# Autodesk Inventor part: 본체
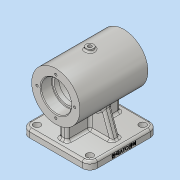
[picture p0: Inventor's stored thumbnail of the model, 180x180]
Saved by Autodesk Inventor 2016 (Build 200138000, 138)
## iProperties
Created: 2019-06
Part Number: 본체
Material: 알루미늄 6061
Document SubType Name: Modeling
Designer: Administrator
Mass: 610.373 g
Surface Area: 622.717 cm^2
Volume: 226.064 cm^3
Density: 2.7 g/cm^3
Appearance: 알루미늄 - 평지
Author: Administrator
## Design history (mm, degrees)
sketch "스케치1"
  geometry: C1 r 32 at (0, 0); 1 further point
  constraints: 1 centre point, 1 coincident
  dimensions: "d0" = 64 diameter of C1
extrude "돌출1" new body sketch "스케치1" stored distance "d1" = 90; taper "d2" = 0 deg
sketch "스케치2"
  geometry: L1 (45, -55)-(-45, -55); L2 (-45, -55)-(-45, -65); L3 (-45, -65)-(45, -65); L4 (45, -65)-(45, -55); 2 further points
  constraints: 8 end point, 2 parallel, 1 horizontal, 1 midpoint, 1 perpendicular, 1 vertical alignment
  dimensions: "d3" = 90 distance of L2.end L3.end; "d4" = 10 distance of L1.end L2.end; "d5" = 65 distance from line of L3 point (0, 0)
extrude "돌출2" join sketch "스케치2" stored distance "d6" = 90; taper "d7" = 0 deg
sketch "스케치3"
  geometry: L1 (40, -10)-(50, -10); L2 (50, -10)-(50, -80); L3 (50, -80)-(40, -80); L4 (40, -80)-(40, -10); L5 (40, -10)-(50, -80); L6 (50, -10)-(40, -80); 1 further point
  constraints: 12 end point, 2 midpoint, 2 parallel, 1 horizontal, 1 perpendicular
  dimensions: "d8" = 10 distance of L2.end L3.end; "d9" = 70 distance of L1.end L2.end
extrude "돌출3" join sketch "스케치3" stored distance "d10" = 90; taper "d11" = 0 deg
sketch "스케치4"
  geometry: L1 (45, -55)-(-45, -55) reference; L2 (-35, -55)-(-28.281, -36.539); L3 (-45, -55)-(-45, -65) reference; 1 further point
  constraints: 2 end point, 1 point on line
  dimensions: "d12" = 110 deg angle of L1 L2; "d13" = 10 distance from line of L3 L2.start
feature "리브1" sketch "스케치4" dims "d14" = 1, "d15" = 10, "d16" = 0, "d17" = 0, "d18" = 1, "d19" = 1
sketch "스케치5"
  geometry: L1 (-45, 32)-(-45, -32) reference; L2 (-45, 0)-(45, 0); L3 (45, -32)-(45, 32) reference; L4 (-45, 0)-(-45, 20); L5 (-45, 20)-(-30, 20); L6 (-30, 20)-(-30, 17); L7 (-30, 17)-(-24, 17); L8 (-24, 17)-(-24, 25); L9 (-24, 25)-(24, 25); L10 (24, 25)-(24, 17); L11 (24, 17)-(30, 17); L12 (30, 17)-(30, 20); L13 (30, 20)-(45, 20); L14 (45, 20)-(45, 0); 3 further points
  constraints: 24 end point, 9 perpendicular, 4 midpoint, 2 point on line, 1 horizontal, 1 vertical alignment
  dimensions: "d20" = 40 diameter of L5 L2; "d21" = 34 diameter of L7 L2; "d22" = 50 diameter of L9 L2; "d23" = 40 diameter of L13 L2; "d24" = 34 diameter of L11 L2; "d25" = 15 distance of L4.end L5.end; "d26" = 48 distance of L8.end L9.end; "d27" = 15 distance of L12.end L13.end
revolve "회전1" sketch "스케치5" stored, may be unused: angle "d28" = 90 deg
node "작업 평면1"
sketch "스케치6"
  geometry: C1 r 5 at (45, 45); 1 further point
  constraints: 1 centre point, 1 coincident
  dimensions: "d30" = 10 diameter of C1
extrude "돌출4" join sketch "스케치6" stored distance "d31" = 90; taper "d32" = 0 deg
hole "구멍1" diameter "d35" = 4.917; stored, may be unused: countersink angle "d39" = 90 deg, drill point angle "d41" = 118 deg; dims "d33" = 10, "d34" = 10, "d36" = 12, "d37" = 4, "d38" = 2, "d40" = 17.1
fillet "모깎기1" dims "d42" = 10
hole "구멍2" diameter "d45" = 9; stored, may be unused: countersink angle "d49" = 90 deg, drill point angle "d51" = 118 deg; dims "d43" = 10, "d44" = 10, "d46" = 12, "d47" = 4, "d48" = 2, "d50" = 17.1
sketch "스케치7"
  geometry: L1 (72, -5)-(61.34, -5); L2 (-5, -8)-(-5, -18.66); L3 (-5, -85)-(8.66, -85); L4 (75, -85)-(75, -71.34); L5 (75, -5)-(-5, -85); L6 (-5, -5)-(75, -85); L7 (75, -67.155)-(75, -22.845); L8 (61.34, -85)-(75, -85); L9 (12.845, -85)-(57.155, -85); L10 (-5, -71.34)-(-5, -85); L11 (8.66, -5)-(-2, -5); L12 (-5, -22.845)-(-5, -67.155); L13 (75, -18.66)-(75, -8); L14 (57.155, -5)-(12.845, -5); C1 r 2.458 at (35, -45) reference; C2 r 4.5 at (70, -80) reference; C3 r 4.5 at (0, -80) reference; C4 r 4.5 at (0, -10) reference; C5 r 4.5 at (70, -10) reference; A1 r 10 centre (70, -80) between (61.34, -85) and (75, -71.34); A2 r 10 centre (70, -80) between (62.929, -72.929) and (60.119, -81.538); A3 r 10 centre (70, -80) between (71.538, -70.119) and (62.929, -72.929); A4 r 3 centre (57.155, -82) between (57.155, -85) and (60.119, -81.538); A5 r 3 centre (72, -67.155) between (71.538, -70.119) and (75, -67.155); A6 r 10 centre (0, -80) between (9.881, -81.538) and (-1.538, -70.119); A7 r 10 centre (0, -10) between (-1.538, -19.881) and (9.881, -8.462); A8 r 10 centre (0, -80) between (-5, -71.34) and (8.66, -85); A9 r 3 centre (12.845, -82) between (9.881, -81.538) and (12.845, -85); A10 r 3 centre (-2, -67.155) between (-5, -67.155) and (-1.538, -70.119); A11 r 10 centre (0, -10) between (8.66, -5) and (-5, -18.66); A12 r 3 centre (-2, -8) between (-2, -5) and (-5, -8); A13 r 3 centre (-2, -22.845) between (-1.538, -19.881) and (-5, -22.845); A14 r 3 centre (12.845, -8) between (12.845, -5) and (9.881, -8.462); A15 r 10 centre (70, -10) between (60.119, -8.462) and (71.538, -19.881); A16 r 10 centre (70, -10) between (75, -18.66) and (61.34, -5); A17 r 3 centre (72, -8) between (75, -8) and (72, -5); A18 r 3 centre (72, -22.845) between (75, -22.845) and (71.538, -19.881); A19 r 3 centre (57.155, -8) between (60.119, -8.462) and (57.155, -5); 1 further point
  constraints: 46 point on circle, 28 end point, 24 tangent, 19 centre point, 18 parallel, 13 point on line, 9 perpendicular, 6 equal radius, 4 coincident, 3 horizontal, 2 midpoint
  dimensions: "d52" = 80 distance of L4.start L3.start; "d53" = 80 distance of L3.start L6.start; "d54" = 10 radius of A1; "d55" = 3 radius of A4; "d56" = 10 radius of A6; "d57" = 10 radius of A7; "d58" = 3 radius of A9; "d59" = 3 radius of A12; "d60" = 10 radius of A15; "d61" = 3 radius of A17
extrude "돌출5" cut sketch "스케치7" distance "d62" = 5; taper "d63" = 0 deg
sketch "스케치8"
  geometry: 2 further points
  constraints: 1 vertical alignment
  dimensions: "d64" = 25 distance of point (0, 0) point (0, 25)
hole "구멍3" sketch "스케치8" at (0, 25) diameter "d65" = 3.242; stored, may be unused: countersink angle "d69" = 90 deg, drill point angle "d71" = 118 deg; dims "d66" = 7, "d67" = 4, "d68" = 2, "d70" = 9
sketch "스케치9"
  geometry: L1 (0, -10)-(10, -10) reference; L2 (10, 0)-(10, 70) reference; 2 further points
  constraints: 1 other
  dimensions: "d75" = 45 distance from line of L1 point (6, 35); "d76" = 4 distance from line of L2 point (6, 35)
feature "엠보싱1" sketch "스케치9" dims "d1" = 90, "d77" = 0.5, "d78" = 0
fillet "모깎기2" dims "d79" = 3
fillet "모깎기3" dims "d80" = 0.6
fillet "모깎기4" dims "d81" = 2
fillet "모깎기5" dims "d82" = 3
fillet "모깎기6" dims "d83" = 3
chamfer "모따기1" distance "d84" = 1; stored, may be unused: second distance "d85" = 2, angle "d86" = 45 deg
node "솔리드1"
mirror "대칭1"
mirror "대칭2"
mirror "대칭3"
pattern_circular "원형 패턴1" dims angle "d73" = 360 deg
mirror "대칭4"
